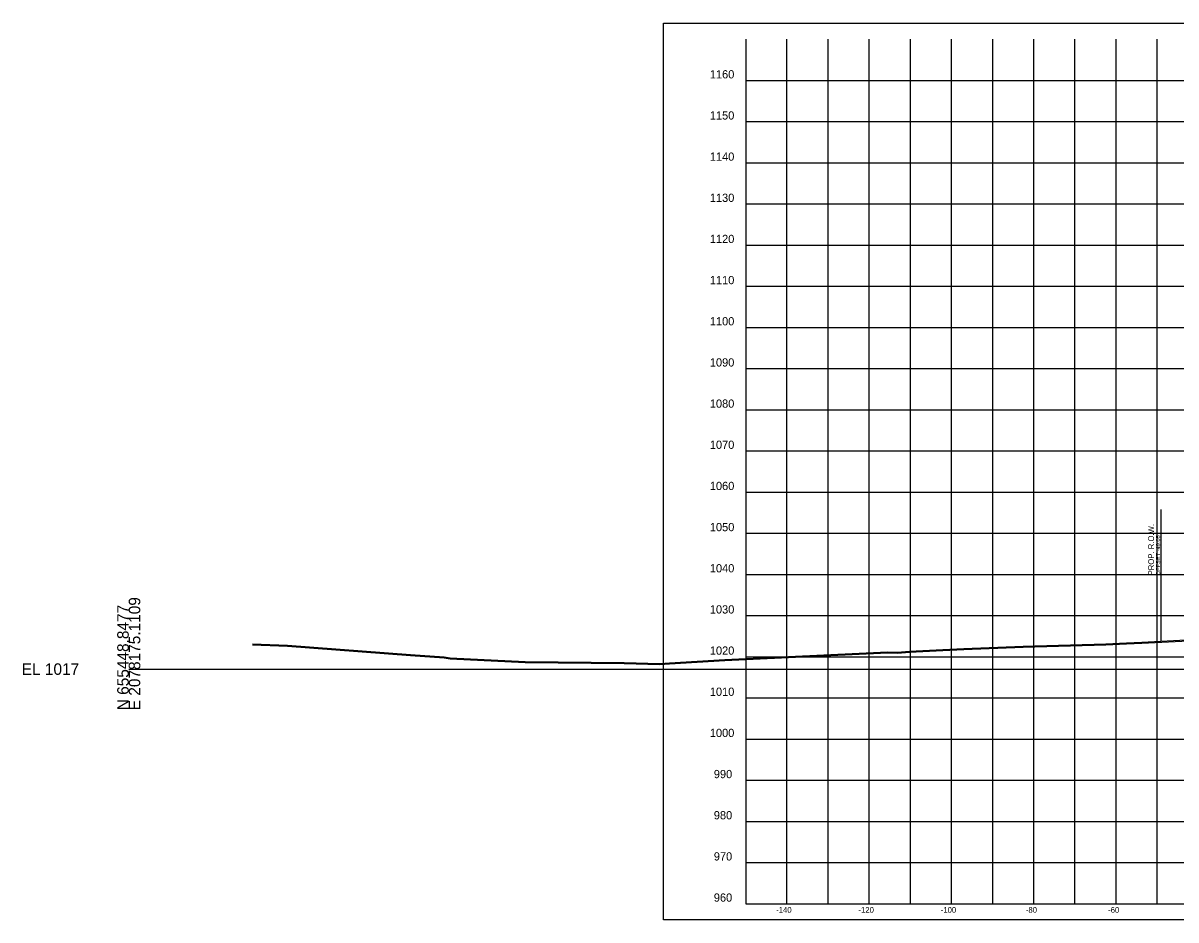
# Model space of a CAD drawing. Extents: x 5868 to 6683, y 2883 to 19120.
# Drawn here: x 5868.1 to 6148.3, y 4884.1 to 5102 of the extents above; entities that cross this region are included whole.
import ezdxf

# ---------------------------------------------------------------- set-up
doc = ezdxf.new("R2010")
doc.units = 0
for name, color, linetype in [('DESIGN - ROW - Right-of-Way and Easement Labels', 7, 'Continuous'), ('DESIGN - ROW - Right-of-Way Linework', 7, 'Continuous'), ('DESIGN - SHEET - Corner Text', 7, 'Continuous'), ('DESIGN - SHEET - Light Grid', 7, 'Continuous'), ('DESIGN - SHEET - Linework', 7, 'Continuous'), ('DESIGN - SHEET - Plot Shape', 7, 'Continuous'), ('SURVEY - GROUND - Bottom of Topsoil Layer', 7, 'Continuous'), ('SURVEY - GROUND - Top of Ground', 7, 'Continuous')]:
    doc.layers.add(name, color=color, linetype=linetype)

msp = doc.modelspace()

# ---------------------------------------------------------------- linework, layer by layer
at = {"layer": 'DESIGN - ROW - Right-of-Way Linework'}
msp.add_line((6144.74, 4951.84), (6144.74, 4983.84), dxfattribs=at)
at = {"layer": 'DESIGN - SHEET - Light Grid'}
msp.add_line((5893.78, 4945.07), (6193.78, 4945.07), dxfattribs=at)
at = {"layer": 'DESIGN - SHEET - Linework'}
for p, q in [((6053.78, 4888.07), (6053.78, 5098.07)), ((6063.78, 4888.07), (6063.78, 5098.07)), ((6073.78, 4888.07), (6073.78, 5098.07)), ((6083.78, 4888.07), (6083.78, 5098.07)), ((6093.78, 4888.07), (6093.78, 5098.07)), ((6103.78, 4888.07), (6103.78, 5098.07)), ((6113.78, 4888.07), (6113.78, 5098.07)), ((6123.78, 4888.07), (6123.78, 5098.07)), ((6133.78, 4888.07), (6133.78, 5098.07)), ((6143.78, 4888.07), (6143.78, 5098.07)), ((6043.78, 5088.07), (6343.78, 5088.07)), ((6043.78, 5078.07), (6343.78, 5078.07)), ((6043.78, 5068.07), (6343.78, 5068.07)), ((6043.78, 5058.07), (6343.78, 5058.07)), ((6043.78, 5048.07), (6343.78, 5048.07)), ((6043.78, 5038.07), (6343.78, 5038.07)), ((6043.78, 5028.07), (6343.78, 5028.07)), ((6043.78, 5018.07), (6343.78, 5018.07)), ((6043.78, 5008.07), (6343.78, 5008.07)), ((6043.78, 4998.07), (6343.78, 4998.07)), ((6043.78, 4988.07), (6343.78, 4988.07)), ((6043.78, 4978.07), (6343.78, 4978.07)), ((6043.78, 4968.07), (6343.78, 4968.07)), ((6043.78, 4958.07), (6343.78, 4958.07)), ((6043.78, 4948.07), (6343.78, 4948.07)), ((6043.78, 4938.07), (6343.78, 4938.07)), ((6043.78, 4928.07), (6343.78, 4928.07)), ((6043.78, 4918.07), (6343.78, 4918.07)), ((6043.78, 4908.07), (6343.78, 4908.07)), ((6043.78, 4898.07), (6343.78, 4898.07))]:
    msp.add_line(p, q, dxfattribs=at)
msp.add_lwpolyline([(6043.78, 5098.07), (6043.78, 4888.07), (6343.78, 4888.07), (6343.78, 5098.07)], dxfattribs=at)
at = {"layer": 'DESIGN - SHEET - Plot Shape'}
msp.add_lwpolyline([(6023.78, 5102.01), (6363.78, 5102.01), (6363.78, 4884.13), (6023.78, 4884.13)], close=True, dxfattribs=at)
at = {"layer": 'SURVEY - GROUND - Bottom of Topsoil Layer'}
for p, q in [((6140.02, 4951.34), (6169.24, 4952.91)), ((5923.85, 4950.97), (5932.33, 4950.61)), ((5932.33, 4950.61), (5962.3, 4948.36)), ((6038.65, 4947.15), (6078.19, 4949.02)), ((6078.19, 4949.02), (6080.63, 4948.97)), ((6080.63, 4948.97), (6083.55, 4949.15)), ((6083.55, 4949.15), (6091.65, 4949.59)), ((6091.65, 4949.59), (6096.8, 4949.8)), ((6096.8, 4949.8), (6111.23, 4950.4)), ((6111.23, 4950.4), (6131.27, 4950.95)), ((6131.27, 4950.95), (6136.3, 4951.21)), ((6136.3, 4951.21), (6140.02, 4951.34)), ((5962.3, 4948.36), (5970.44, 4947.77)), ((5970.44, 4947.77), (5971.9, 4947.56)), ((5971.9, 4947.56), (5990.18, 4946.65)), ((5990.18, 4946.65), (6014.21, 4946.42)), ((6014.21, 4946.42), (6022.87, 4946.2)), ((6022.87, 4946.2), (6025.22, 4946.33)), ((6025.22, 4946.33), (6038.65, 4947.15))]:
    msp.add_line(p, q, dxfattribs=at)
at = {"layer": 'SURVEY - GROUND - Top of Ground'}
msp.add_lwpolyline([(5923.85, 4951.22), (5932.33, 4950.86), (5962.3, 4948.61), (5970.44, 4948.02), (5971.9, 4947.81), (5990.18, 4946.9), (6014.21, 4946.67), (6022.87, 4946.45), (6025.22, 4946.58), (6038.65, 4947.4), (6078.19, 4949.27), (6080.63, 4949.22), (6083.55, 4949.4), (6091.65, 4949.84), (6096.8, 4950.05), (6111.23, 4950.65), (6131.27, 4951.2), (6136.3, 4951.46), (6140.02, 4951.59), (6169.24, 4953.16)], dxfattribs=at)

# ---------------------------------------------------------------- texts
at = {"layer": 'DESIGN - ROW - Right-of-Way and Easement Labels'}
for s, height, p in [('PROP. R.O.W.', 1.4, (6142.99, 4967.84)), ('OFFSET -49.05', 1, (6144.49, 4967.84))]:
    msp.add_text(s, height=height, rotation=90, dxfattribs=at).set_placement(p)
at = {"layer": 'DESIGN - SHEET - Corner Text'}
for s, height, p in [('1160', 2, (6035.03, 5088.57)), ('1150', 2, (6035.03, 5078.57)), ('1140', 2, (6035.03, 5068.57)), ('1130', 2, (6035.03, 5058.57)), ('1120', 2, (6035.03, 5048.57)), ('1110', 2, (6035.03, 5038.57)), ('1100', 2, (6035.03, 5028.57)), ('1090', 2, (6035.03, 5018.57)), ('1080', 2, (6035.03, 5008.57)), ('1070', 2, (6035.03, 4998.57)), ('1060', 2, (6035.03, 4988.57)), ('1050', 2, (6035.03, 4978.57)), ('1040', 2, (6035.03, 4968.57)), ('1030', 2, (6035.03, 4958.57)), ('1020', 2, (6035.03, 4948.57)), ('1010', 2, (6035.03, 4938.57)), ('1000', 2, (6035.03, 4928.57)), ('990', 2, (6036, 4918.57)), ('980', 2, (6036, 4908.57)), ('970', 2, (6036, 4898.57)), ('960', 2, (6036, 4888.57)), ('-140', 1.4, (6051.16, 4885.87)), ('-120', 1.4, (6071.16, 4885.87)), ('-100', 1.4, (6091.16, 4885.87)), ('-80', 1.4, (6111.84, 4885.87)), ('-60', 1.4, (6131.84, 4885.87))]:
    msp.add_text(s, height=height, dxfattribs=at).set_placement(p)
at = {"layer": 'DESIGN - SHEET - Light Grid'}
for s, p in [('N 655448.8477', (5893.78, 4935.07)), ('E 2078175.1109', (5896.58, 4935.07))]:
    msp.add_text(s, height=2.8, rotation=90, dxfattribs=at).set_placement(p)
msp.add_text('EL 1017', height=2.8, dxfattribs=at).set_placement((5867.78, 4943.67))

doc.saveas('drawing.dxf')
